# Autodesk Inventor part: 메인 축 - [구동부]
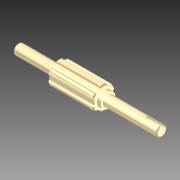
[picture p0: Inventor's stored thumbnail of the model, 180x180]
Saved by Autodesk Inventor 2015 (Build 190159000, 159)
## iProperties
Company: 한국ATC센터
Created: 2014-07
Part Number: 메인 축 - [구동부]
Document SubType Name: 모델링
Designer: KYOUNG IL JANG
Mass: 168.352 g
Surface Area: 72.5104 cm^2
Volume: 21.4461 cm^3
Density: 7.85 g/cm^3
Material: Steel, Mild
Appearance: Semi-Polished
Author: KYOUNG IL JANG
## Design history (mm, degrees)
revolve "회전1" stored, may be unused: angle "d10" = 90 deg
sketch "스케치2"
  geometry: L1 (2.5, 10.712)-(2.5, 8.646); L2 (-2.5, 10.712)-(-2.5, 8.646); A1 r 9 centre (0, 0) between (2.5, 8.646) and (-2.5, 8.646) reference; A2 r 11 centre (0, 0) between (2.5, 10.712) and (-2.5, 10.712); 1 further point
  constraints: 4 end point, 4 point on circle, 2 parallel, 1 centre point, 1 coincident, 1 vertical
  dimensions: "d11" = 22 diameter of A2; "d12" = 5 distance between parallel lines of L1 L2
extrude "돌출1" join sketch "스케치2" stored distance "d13" = 10; taper "d14" = 0 deg
chamfer "모따기1" distance "d15" = 1; stored, may be unused: second distance "d16" = 2, angle "d17" = 45 deg
node "작업 평면1"
node "작업 평면2"
sketch "스케치3"
  geometry: L1 (2.5, 10.712)-(2.5, 10.198); L2 (-2.5, 10.712)-(-2.5, 10.198); A1 r 11 centre (0, 0) between (2.5, 10.712) and (-2.5, 10.712) reference; A2 r 10.5 centre (0, 0) between (2.5, 10.198) and (-2.5, 10.198); 1 further point
  constraints: 4 end point, 2 point on circle, 1 centre point, 1 coincident, 1 parallel, 1 vertical
  dimensions: "d19" = 21 diameter of A2
extrude "돌출2" cut sketch "스케치3" distance "d20" = 1.35; taper "d21" = 0 deg
node "작업 평면3"
sketch "스케치4"
  geometry: L1 (-26, -5)-(-26, 5) reference; L2 (-26, 1.5)-(-12.5, 1.5); L3 (-12.5, -1.5)-(-26, -1.5); A1 r 1.5 centre (-12.5, 0) between (-12.5, -1.5) and (-12.5, 1.5); 2 further points
  constraints: 4 end point, 2 perpendicular, 2 point on circle, 2 point on line, 2 tangent, 1 centre point, 1 horizontal alignment, 1 midpoint
  dimensions: "d25" = 3 distance between parallel lines of L3 L2; "d26" = 15 dimension on A1 L1
extrude "돌출3" cut sketch "스케치4" distance "d27" = 1.8; taper "d28" = 0 deg
chamfer "모따기2" distance "d29" = 1; stored, may be unused: second distance "d30" = 2, angle "d31" = 45 deg
node "솔리드1"
node "솔리드 본체"
node "곡면 본체"
mirror "대칭1"
pattern_circular "원형 패턴1" dims "d23" = 360 deg
sketch "스케치1"
  geometry: L1 (-69.5, 0)-(69.5, 0); L2 (69.5, 0)-(69.5, 5); L3 (69.5, 5)-(55.5, 5); L4 (55.5, 5)-(55.5, 4.8); L5 (55.5, 4.8)-(54.35, 4.8); L6 (54.35, 4.8)-(54.35, 5); L7 (54.35, 5)-(30.5, 5); L8 (30.5, 5)-(30.5, 9); L9 (30.5, 9)-(-13.5, 9); L10 (-13.5, 9)-(-13.5, 7); L11 (-13.5, 7)-(-17.5, 7); L12 (-17.5, 7)-(-17.5, 5); L13 (-17.5, 5)-(-69.5, 5); L14 (-69.5, 5)-(-69.5, 0); 2 further points
  constraints: 28 end point, 9 parallel, 4 collinear, 2 perpendicular, 1 coincident, 1 horizontal, 1 midpoint
  dimensions: "d2" = 1.15 distance between parallel lines of L6 L4; "d3" = 10 diameter of L3 L1; "d4" = 9.6 diameter of L5 L1; "d6" = 44 distance between parallel lines of L10 L8; "d7" = 4 distance between parallel lines of L12 L10; "d8" = 14 diameter of L11 L1; "d9" = 18 diameter of L9 L1; "d33" = 52 distance from line of L12.end L14; "d37" = 39 distance between parallel lines of L8 L2; "d38" = 14 distance between parallel lines of L2 L4
node "솔리드2"
other parameters: "d18" = -1.65
